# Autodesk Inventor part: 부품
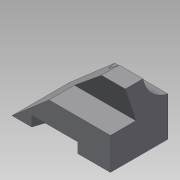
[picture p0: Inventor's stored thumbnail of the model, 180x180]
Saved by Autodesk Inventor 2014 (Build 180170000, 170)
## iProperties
Created: 2015-04
Part Number: 부품
Material: Generic
Document SubType Name: Modeling
Designer: 203-16
Density: 1 g/cm^3
Appearance: Default
Author: 203-16
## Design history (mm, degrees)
sketch "스케치1"
  geometry: L1 (67.5, -39.5)-(-67.5, -39.5); L2 (-67.5, -39.5)-(-67.5, 39.5); L3 (-67.5, 39.5)-(67.5, 39.5); L4 (67.5, 39.5)-(67.5, -39.5); L5 (67.5, -39.5)-(-67.5, 39.5); L6 (-67.5, -39.5)-(67.5, 39.5); 1 further point
  constraints: 12 end point, 2 midpoint, 2 parallel, 1 horizontal, 1 perpendicular
  dimensions: "d0" = 135 distance between parallel lines of L4 L2; "d1" = 79 distance between parallel lines of L1 L3
extrude "돌출1" new body sketch "스케치1" distance "d2" = 89; taper "d3" = 0 deg
sketch "스케치2"
  geometry: L1 (135, 0)-(0, 0) reference; L2 (0, 89)-(135, 89) reference; L3 (0, 0)-(0, 89) reference; L4 (0, 0)-(102.383, 89); L5 (102.383, 89)-(0, 89); L6 (0, 89)-(0, 0); 1 further point
  constraints: 6 end point, 2 collinear, 1 point on line
  dimensions: "d4" = 139 deg angle of L1 L4
extrude "돌출2" cut sketch "스케치2" stored distance "d5" = 89; taper "d6" = 0 deg
sketch "스케치4"
  geometry: L1 (0, 79)-(-89, 79) reference; L2 (-89, 0)-(-89, 79) reference; C1 r 44 at (-97, 88); 1 further point
  constraints: 1 centre point
  dimensions: "d12" = 8 distance from line of C1.centre L2; "d13" = 9 distance from line of L1 C1.centre; "d14" = 44 radius of C1
extrude "돌출4" cut sketch "스케치4" stored distance "d15" = 14; taper "d16" = 0 deg
sketch "스케치5"
  geometry: L1 (-67.5, -39.5)-(67.5, -39.5) reference; L2 (67.5, -39.5)-(67.5, 39.5) reference; L3 (67.5, 39.5)-(-67.5, 39.5) reference; L4 (-48.256, 39.5)-(-22.588, -39.5); L5 (14.831, 39.5)-(40.5, -39.5); L6 (40.5, -39.5)-(-22.588, -39.5); L7 (14.831, 39.5)-(-48.256, 39.5); 1 further point
  constraints: 8 end point, 4 point on line, 2 collinear, 1 parallel
  dimensions: "d17" = 60 distance between parallel lines of L5 L4; "d18" = 72 deg angle of L1 L4; "d19" = 27 distance from line of L2 L5.end
extrude "돌출5" cut sketch "스케치5" distance "d20" = 14; taper "d21" = 0 deg
sketch "스케치8"
  geometry: L1 (-89, 0)-(-89, 44.733) reference; L2 (0, 0)-(-89, 0) reference; L3 (0, 79)-(0, 0) reference; L4 (0, 79)-(-53.93, 79) reference; L5 (-44, 0)-(-44, 35); L6 (-44, 35)-(-89, 20.379); L7 (-89, 20.379)-(-89, 0); L8 (-89, 0)-(-44, 0); 1 further point
  constraints: 8 end point, 2 collinear, 2 point on line, 1 perpendicular
  dimensions: "d25" = 44 distance between parallel lines of L3 L5; "d26" = 72 deg angle of L5 L6; "d27" = 35 distance from line of L5.end L2
extrude "돌출6" cut sketch "스케치8" stored distance "d28" = 14; taper "d29" = 0 deg
node "솔리드1"
